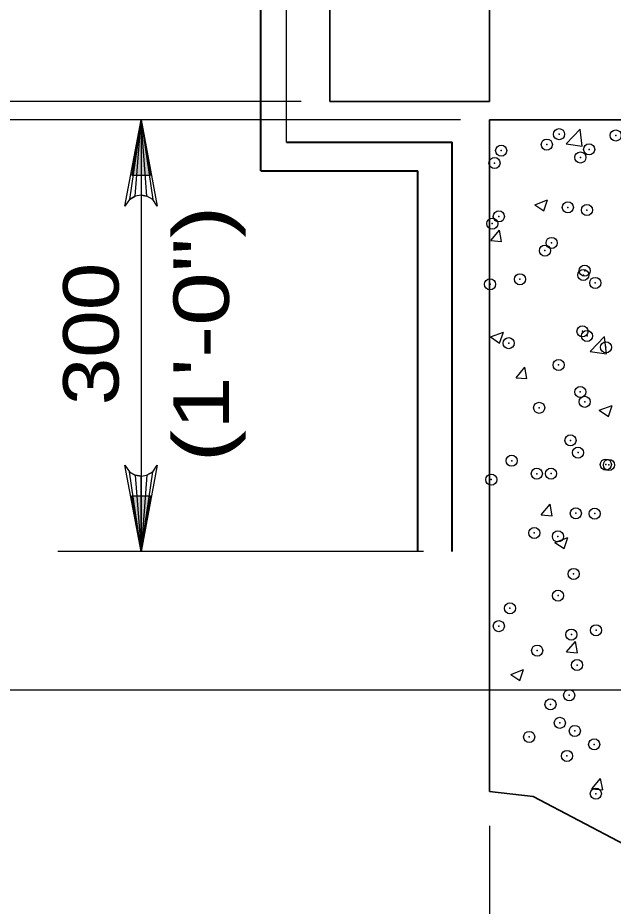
# Model space of a CAD drawing. Extents: x -11 to 79, y -154 to 0.
# Drawn here: x 40.837 to 42.124, y -29.656 to -27.736 of the extents above; entities that cross this region are included whole.
import ezdxf
from ezdxf.enums import TextEntityAlignment as Align

# ---------------------------------------------------------------- set-up
doc = ezdxf.new("R2010")
doc.units = 0
doc.header["$LTSCALE"] = 0.048
doc.header["$PDMODE"] = 32
doc.header["$PDSIZE"] = 0.024
for name, color, linetype, lineweight in [('3', 7, 'Continuous', 25), ('4', 7, 'Continuous', 25), ('5', 7, 'Continuous', 25)]:
    doc.layers.add(name, color=color, linetype=linetype, lineweight=lineweight)

msp = doc.modelspace()

# ---------------------------------------------------------------- hatches: boundary and pattern name
at = {"layer": '3'}
for points in [[(41.084, -28.0765), (41.124, -28.0765), (41.104, -27.9565)], [(41.084, -28.76917), (41.124, -28.76917), (41.104, -28.88917)]]:
    msp.add_hatch(color=256, dxfattribs=at).paths.add_polyline_path(points)

# ---------------------------------------------------------------- linework, layer by layer
for p, q in [((41.44975, -27.91692), (38.566, -27.91692)), ((41.79425, -27.9565), (38.566, -27.9565)), ((41.44975, -27.9565), (39.73308, -27.9565)), ((41.238, -27.9565), (40.924, -27.9565)), ((41.127, -27.9565), (40.924, -27.9565)), ((41.104, -27.9565), (41.104, -28.88917)), ((41.104, -28.0765), (41.104, -28.76917)), ((41.714, -28.88917), (40.924, -28.88917)), ((41.127, -28.88917), (40.924, -28.88917)), ((42.62758, -29.18908), (39.73308, -29.18908)), ((41.85675, -29.482), (41.85675, -30.55392))]:
    msp.add_line(p, q, dxfattribs=at)
for points in [[(41.104, -27.9565), (41.13892, -28.14292), (41.129, -28.12858), (41.1165, -28.12117), (41.104, -28.119), (41.0915, -28.12117), (41.079, -28.12858), (41.06908, -28.14292), (41.104, -27.9565), (41.079, -28.12858), (41.0915, -28.12117), (41.104, -27.9565), (41.104, -28.119), (41.1165, -28.12117), (41.104, -27.9565), (41.129, -28.12858)], [(41.104, -28.88917), (41.06908, -28.70275), (41.079, -28.71708), (41.0915, -28.7245), (41.104, -28.72667), (41.1165, -28.7245), (41.129, -28.71708), (41.13892, -28.70275), (41.104, -28.88917), (41.129, -28.71708), (41.1165, -28.7245), (41.104, -28.88917), (41.104, -28.72667), (41.0915, -28.7245), (41.104, -28.88917), (41.079, -28.71708)]]:
    msp.add_lwpolyline(points, dxfattribs=at)
for points in [[(41.084, -28.0765), (41.124, -28.0765), (41.104, -27.9565)], [(41.084, -28.76917), (41.124, -28.76917), (41.104, -28.88917)]]:
    msp.add_lwpolyline(points, close=True, dxfattribs=at)
at = {"layer": '4'}
for p, q in [((42.0225, -28.00842), (42.05317, -27.97642)), ((42.05758, -28.01383), (42.05317, -27.97642)), ((42.0225, -28.00842), (42.0575, -28.01383)), ((41.95508, -28.14017), (41.98267, -28.12958)), ((41.95508, -28.14017), (41.97467, -28.15333)), ((41.97467, -28.15333), (41.98267, -28.12958)), ((41.85975, -28.21758), (41.87875, -28.195)), ((41.88325, -28.21967), (41.87875, -28.195)), ((41.85975, -28.21758), (41.88325, -28.21967)), ((41.85933, -28.42567), (41.88692, -28.41508)), ((41.85933, -28.42567), (41.87892, -28.43883)), ((41.87892, -28.43883), (41.88692, -28.41508)), ((42.07475, -28.45708), (42.10542, -28.42508)), ((42.10975, -28.4625), (42.10542, -28.42517)), ((42.07475, -28.45708), (42.10975, -28.4625)), ((41.91433, -28.51375), (41.93333, -28.49108)), ((41.93792, -28.51583), (41.93333, -28.49117)), ((41.91433, -28.51375), (41.93792, -28.51583)), ((42.09433, -28.58417), (42.12192, -28.57358)), ((42.09433, -28.58417), (42.11392, -28.59733)), ((42.11392, -28.59733), (42.12192, -28.57358)), ((41.969, -28.80992), (41.988, -28.78725)), ((41.9925, -28.81192), (41.988, -28.78725)), ((41.969, -28.80992), (41.9925, -28.81192)), ((41.9985, -28.86967), (42.02608, -28.85908)), ((41.9985, -28.86967), (42.01808, -28.88283)), ((42.01808, -28.88283), (42.02608, -28.85908)), ((42.02358, -29.106), (42.04258, -29.08342)), ((42.04717, -29.10808), (42.04258, -29.08342)), ((42.02358, -29.106), (42.04717, -29.10808)), ((41.90275, -29.15517), (41.93033, -29.14458)), ((41.90275, -29.15517), (41.92233, -29.16833)), ((41.92233, -29.16833), (41.93033, -29.14458)), ((42.07825, -29.40217), (42.09725, -29.3795)), ((42.10175, -29.40425), (42.09725, -29.3795)), ((42.07825, -29.40217), (42.10175, -29.40425))]:
    msp.add_line(p, q, dxfattribs=at)
at = {"layer": '4', "lineweight": 35}
msp.add_lwpolyline([(41.85675, -29.40817), (41.95117, -29.4185), (42.14883, -29.5225), (42.3985, -29.58492), (42.49217, -29.55375), (42.59617, -29.50175), (42.773, -29.48092), (42.98108, -29.46017), (43.15792, -29.38733), (43.32433, -29.40817), (43.45958, -29.4185), (43.56358, -29.3665), (43.62842, -29.39775)], dxfattribs=at)
at = {"layer": '4'}
for p in [(42.00742, -27.98758), (42.12992, -27.99042), (41.98083, -28.01008), (42.07233, -28.02033), (41.88225, -28.02308), (42.0535, -28.03792), (41.86783, -28.04992), (42.02633, -28.14575), (42.0675, -28.15142), (41.87725, -28.16533), (41.86308, -28.18092), (41.99117, -28.2225), (41.97683, -28.23908), (42.06275, -28.2825), (41.92283, -28.301), (42.05992, -28.29192), (42.0855, -28.30892), (41.85825, -28.312), (42.05792, -28.41358), (42.06783, -28.42358), (41.8985, -28.43917), (42.10867, -28.44808), (42.00625, -28.48617), (42.05317, -28.54458), (42.06283, -28.56583), (41.96433, -28.57883), (42.032, -28.64925), (42.04842, -28.67567), (41.90492, -28.69325), (42.10842, -28.7015), (42.11508, -28.70217), (41.95925, -28.72117), (41.99, -28.72108), (41.86075, -28.73408), (42.04358, -28.80675), (42.08433, -28.8075), (41.95375, -28.84933), (42.00483, -28.85675), (42.03883, -28.93775), (42.00517, -28.98467), (41.90125, -29.01208), (41.87708, -29.05058), (42.034, -29.06883), (42.08725, -29.05942), (41.96008, -29.10342), (42.04633, -29.13458), (42.02925, -29.19992), (41.98883, -29.21958), (42.00892, -29.25958), (42.04133, -29.27692), (41.94275, -29.28992), (42.08325, -29.306), (42.02442, -29.331), (42.08683, -29.41258)]:
    msp.add_point(p, dxfattribs=at)
at = {"layer": '5', "lineweight": 40}
for p, q in [((41.3625, -28.0665), (41.3625, -25.07242)), ((41.41825, -28.0045), (41.7765, -28.0045)), ((41.7765, -28.88917), (41.7765, -28.0045)), ((41.3625, -28.0665), (41.70217, -28.0665)), ((41.70217, -28.88917), (41.70217, -28.0665))]:
    msp.add_line(p, q, dxfattribs=at)
at = {"layer": '5'}
msp.add_line((41.41825, -28.0045), (41.41825, -25.13433), dxfattribs=at)
at = {"layer": '5', "lineweight": 35}
for p, q in [((41.51225, -27.91692), (41.51225, -25.18558)), ((41.85675, -27.91692), (41.85675, -25.61242)), ((41.51225, -27.91692), (41.85675, -27.91692)), ((41.85675, -29.40817), (41.85675, -27.9565)), ((41.85675, -27.9565), (43.62842, -27.9565))]:
    msp.add_line(p, q, dxfattribs=at)

# ---------------------------------------------------------------- texts
at = {"layer": '3'}
for s, width, p in [('(1\'-0")', 1.3, (41.29383, -28.41929)), ('300', 1.15, (41.0555, -28.41929))]:
    msp.add_text(s, height=0.12, rotation=90, dxfattribs=dict(at, width=width)).set_placement(p, align=Align.CENTER)

doc.saveas('drawing.dxf')
